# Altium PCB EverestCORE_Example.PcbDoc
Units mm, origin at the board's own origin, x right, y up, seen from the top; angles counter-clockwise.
Board outline 100 x 100 mm, 6 copper layers (Top Layer, Mid-Layer 1, Mid-Layer 2, Mid-Layer 3, Mid-Layer 4, Bottom Layer), stack 1.62 mm thick; 18 components, 52 nets, 312 pads, 67 vias.
Unrouted connection lines stored in the file: 17.
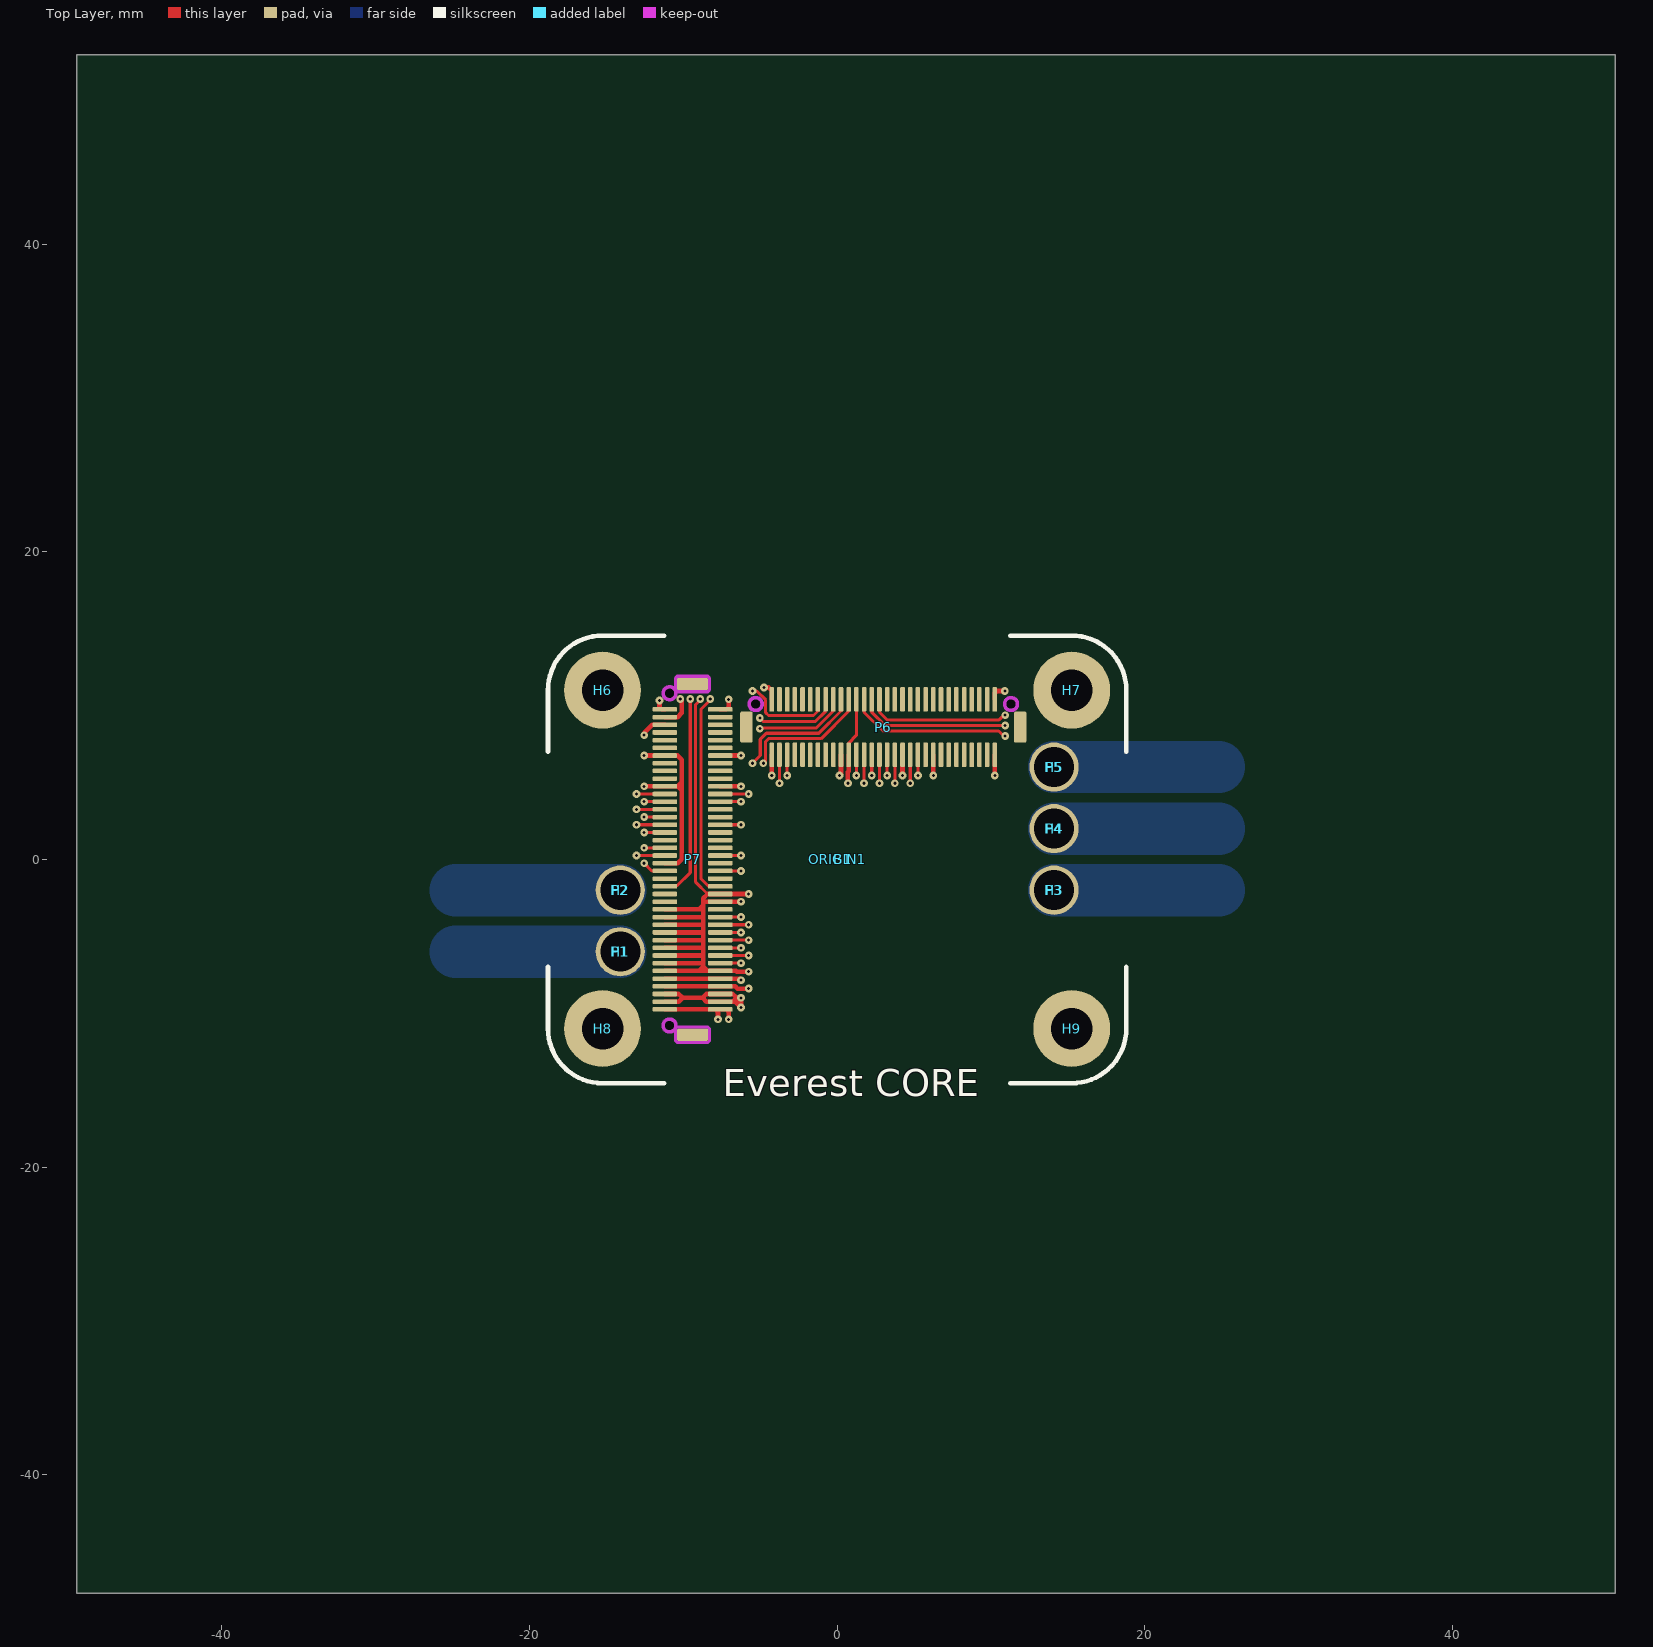
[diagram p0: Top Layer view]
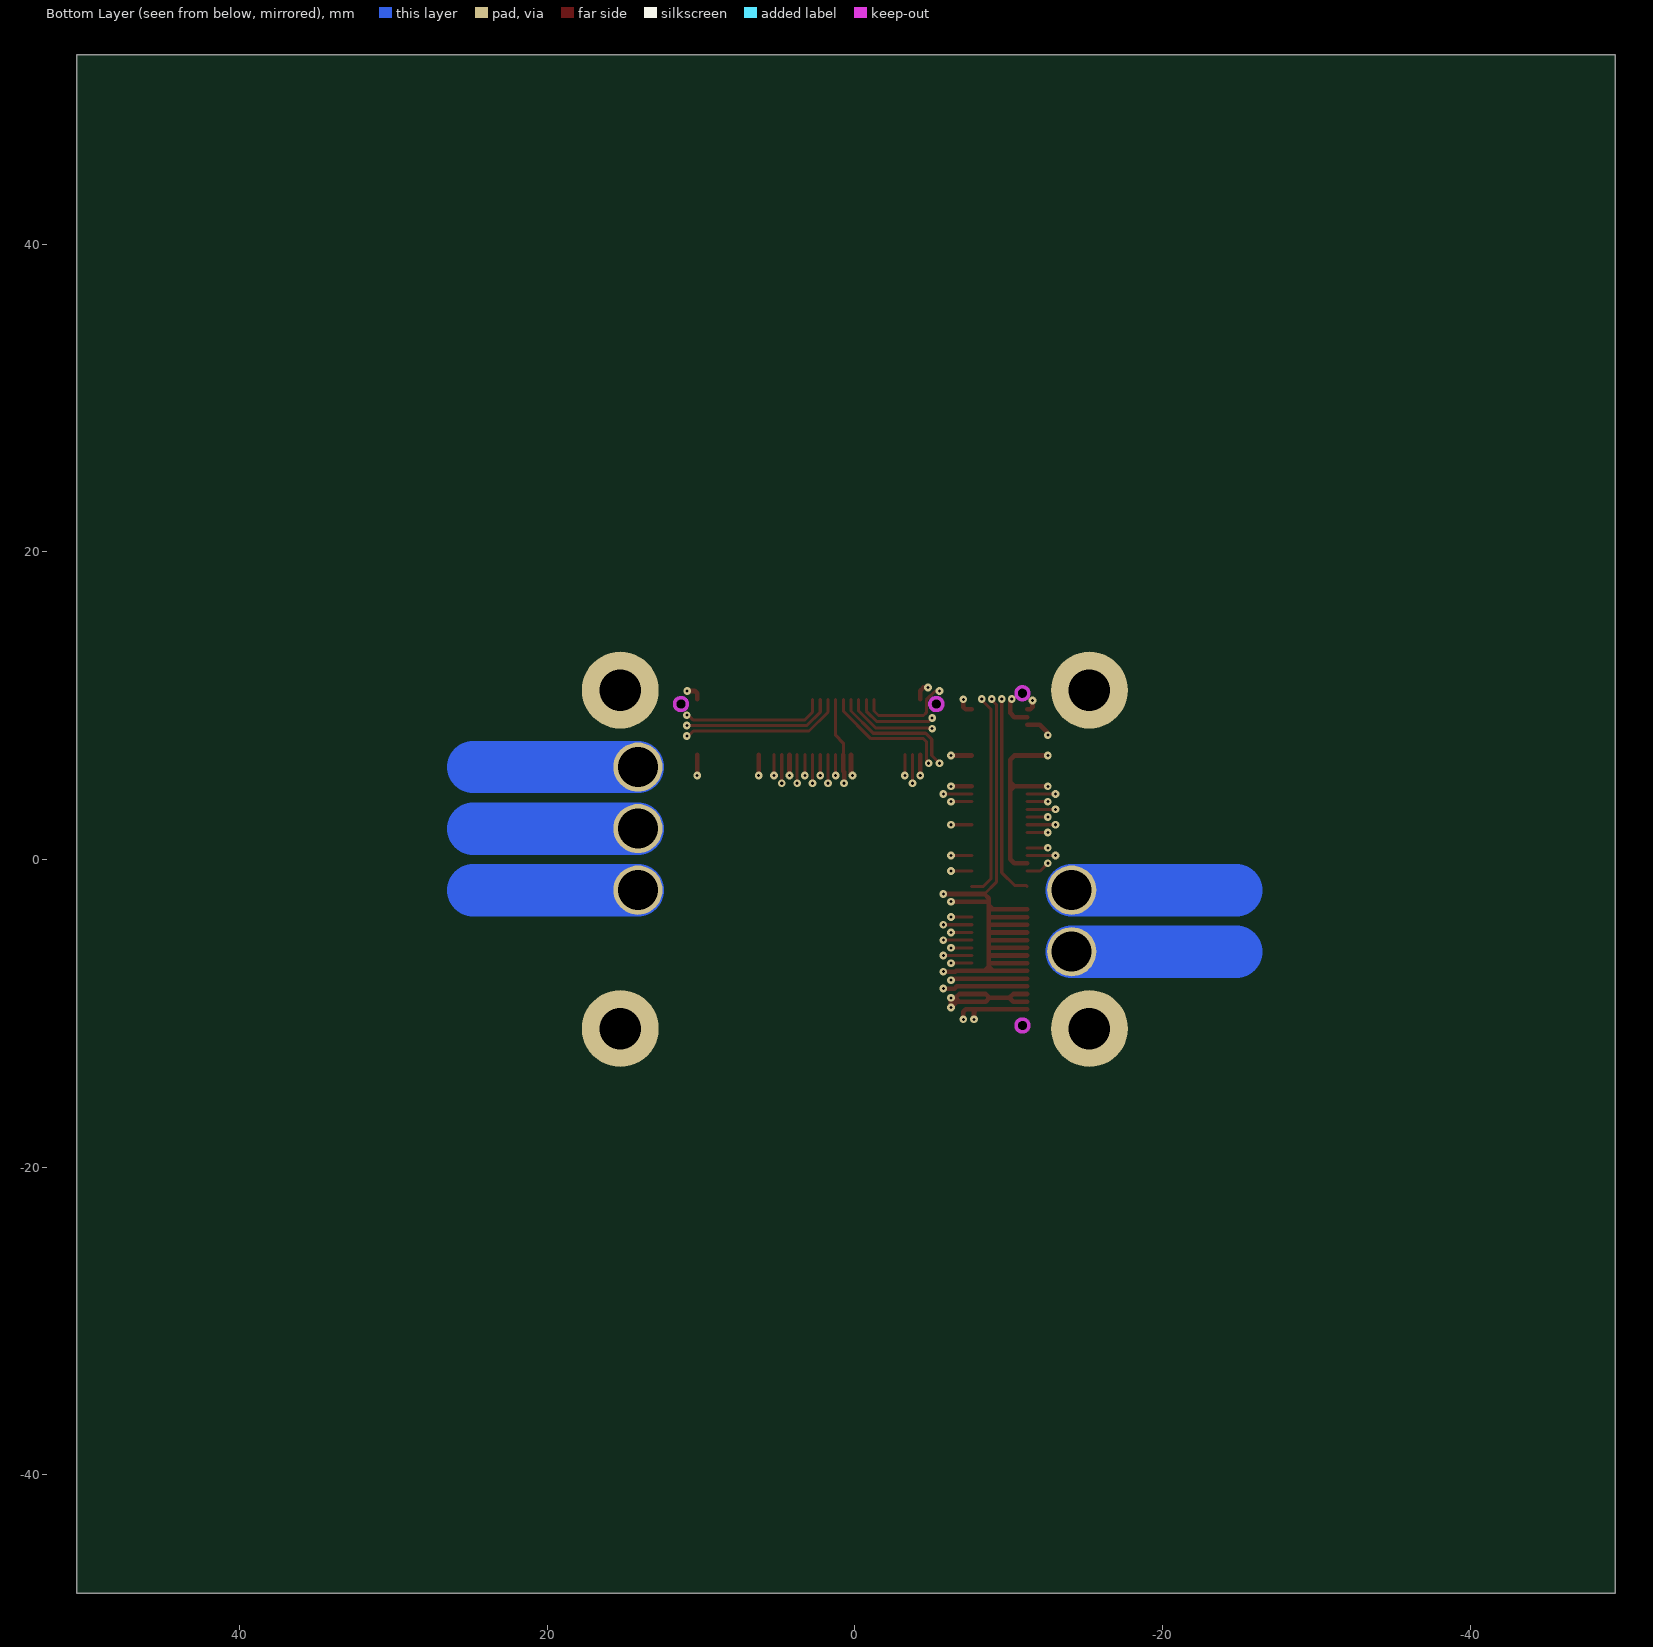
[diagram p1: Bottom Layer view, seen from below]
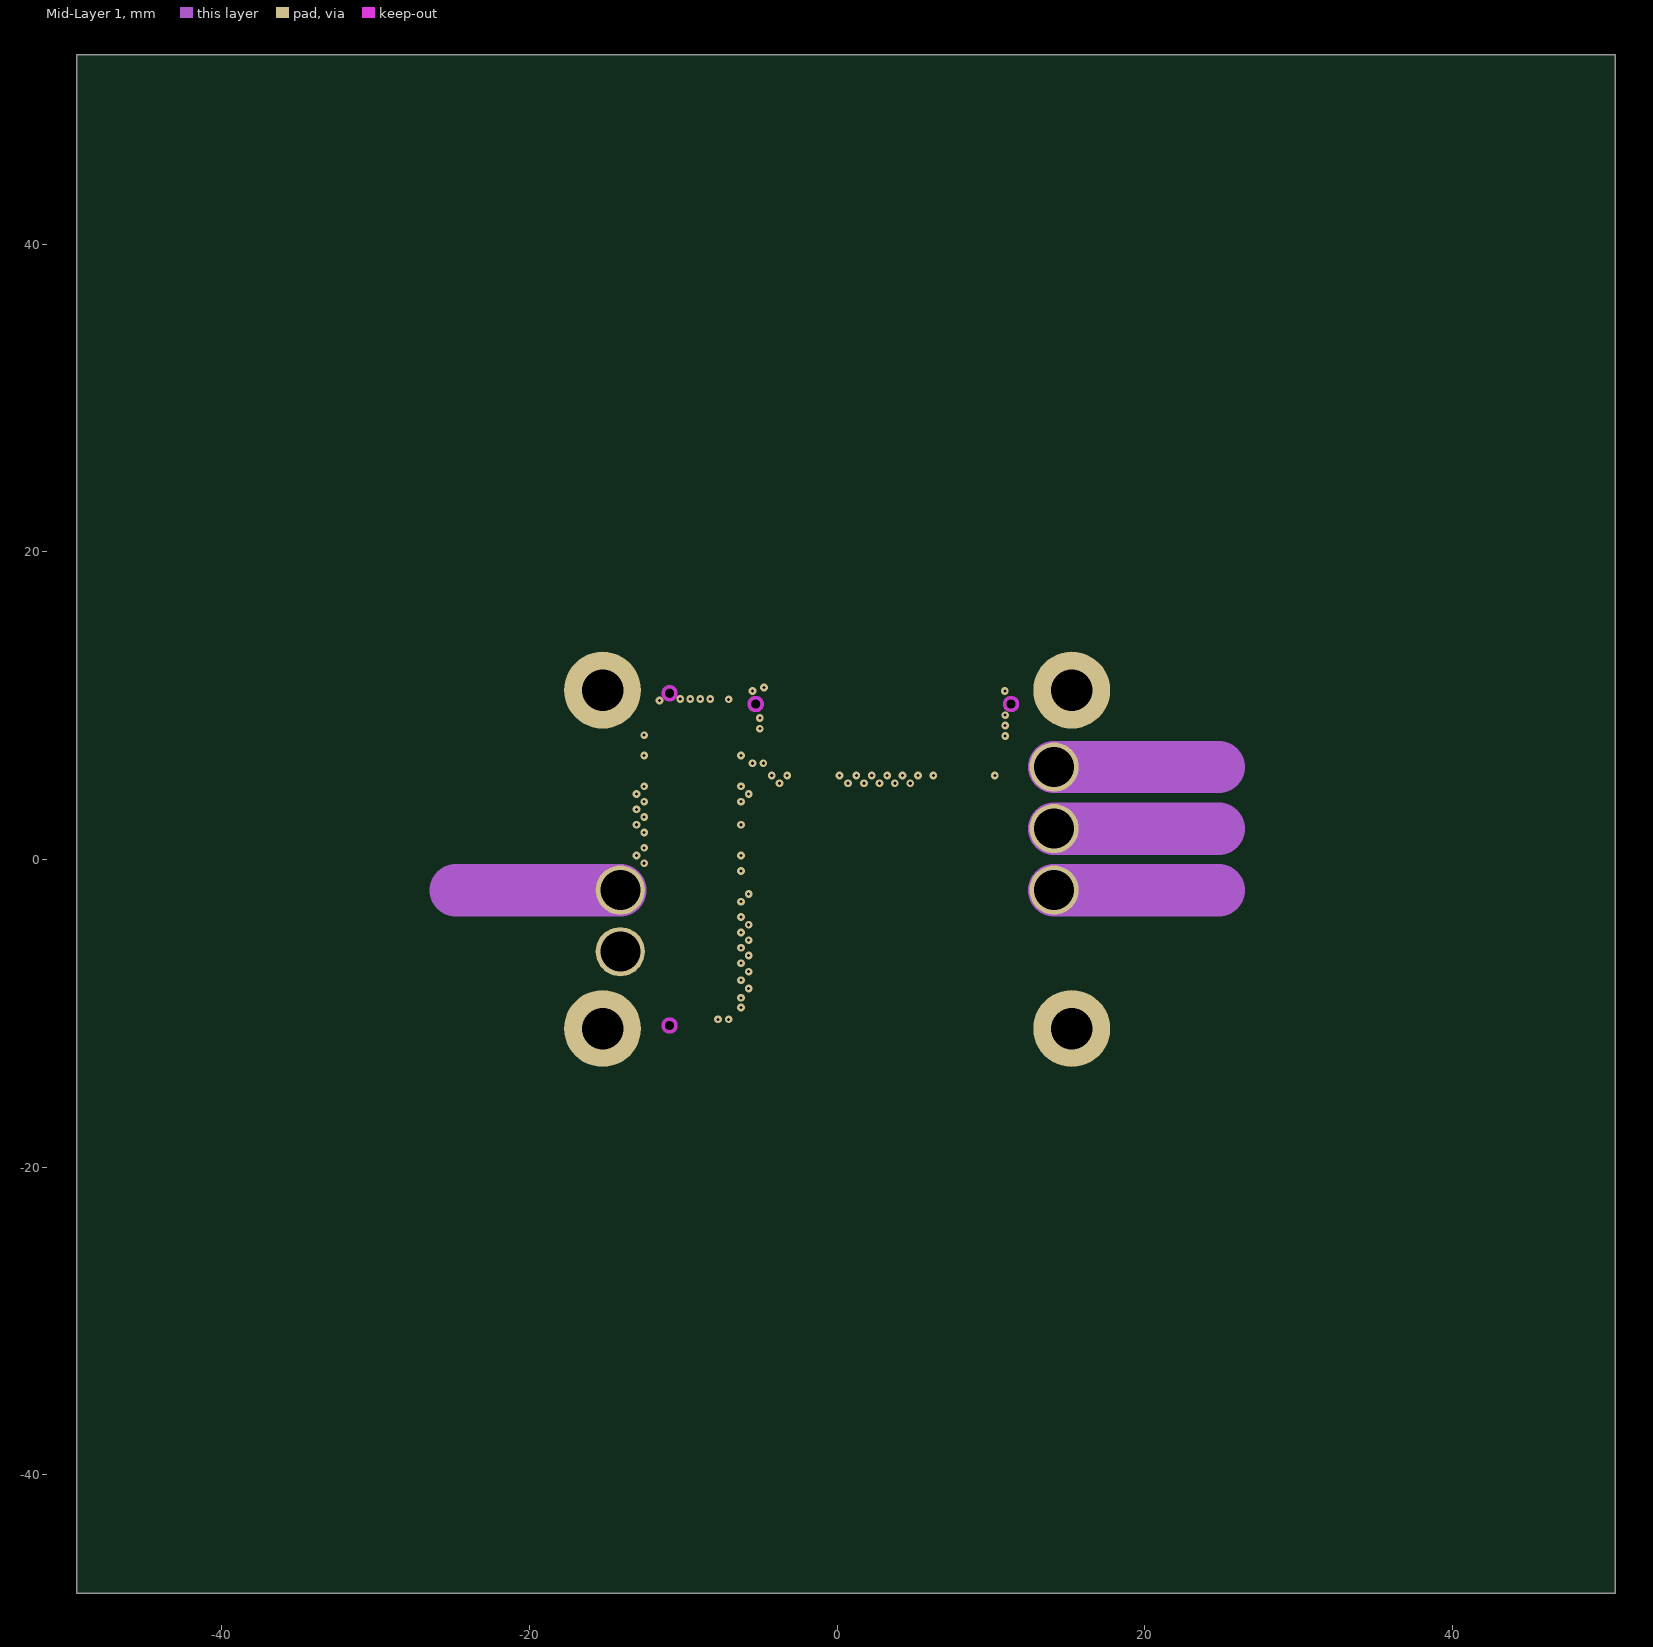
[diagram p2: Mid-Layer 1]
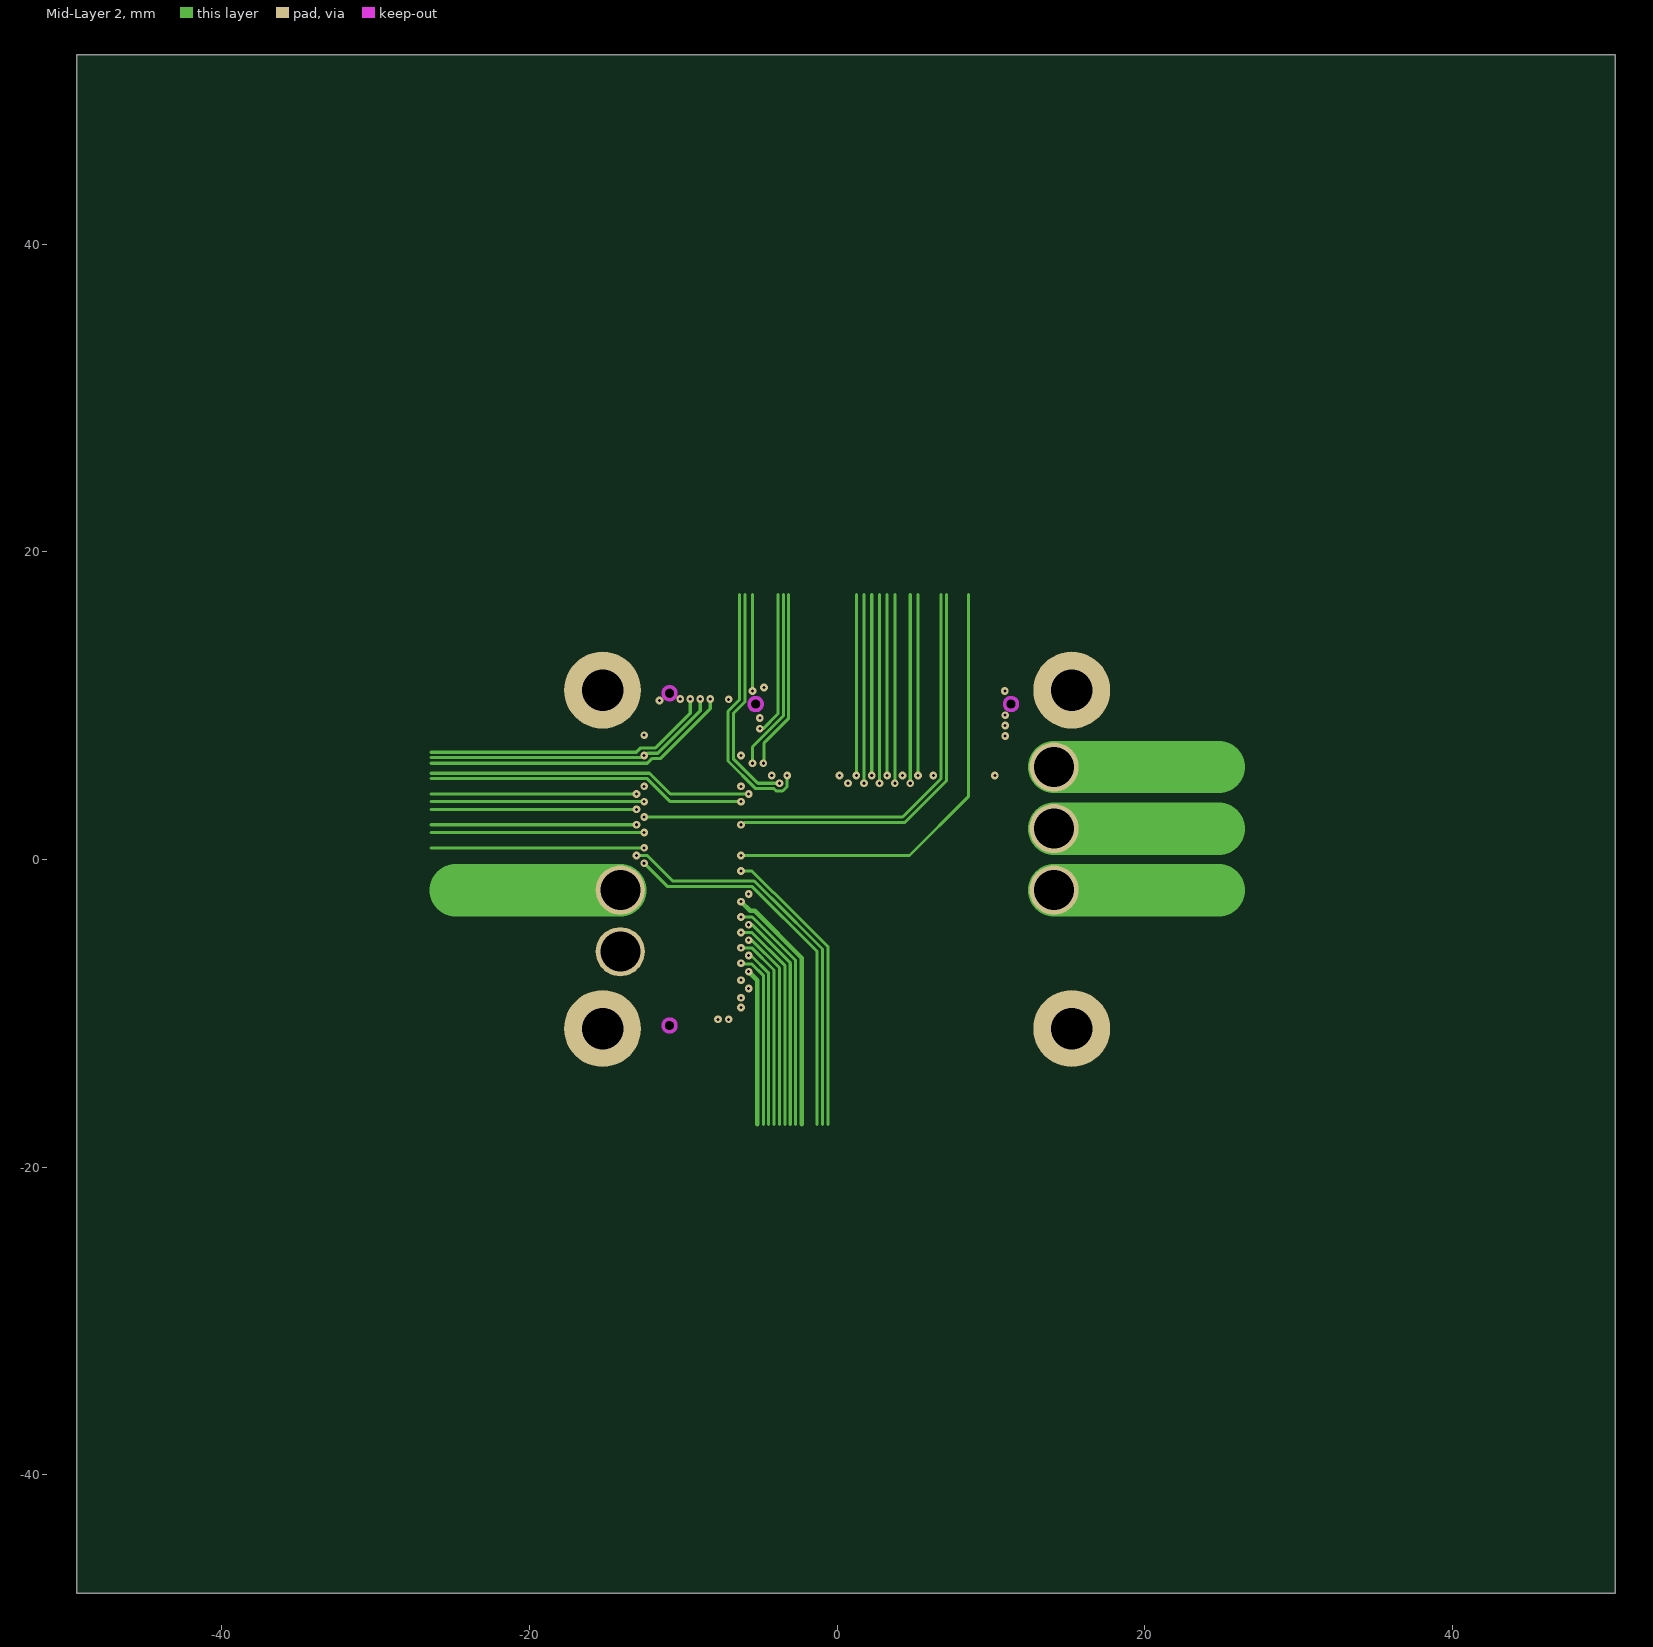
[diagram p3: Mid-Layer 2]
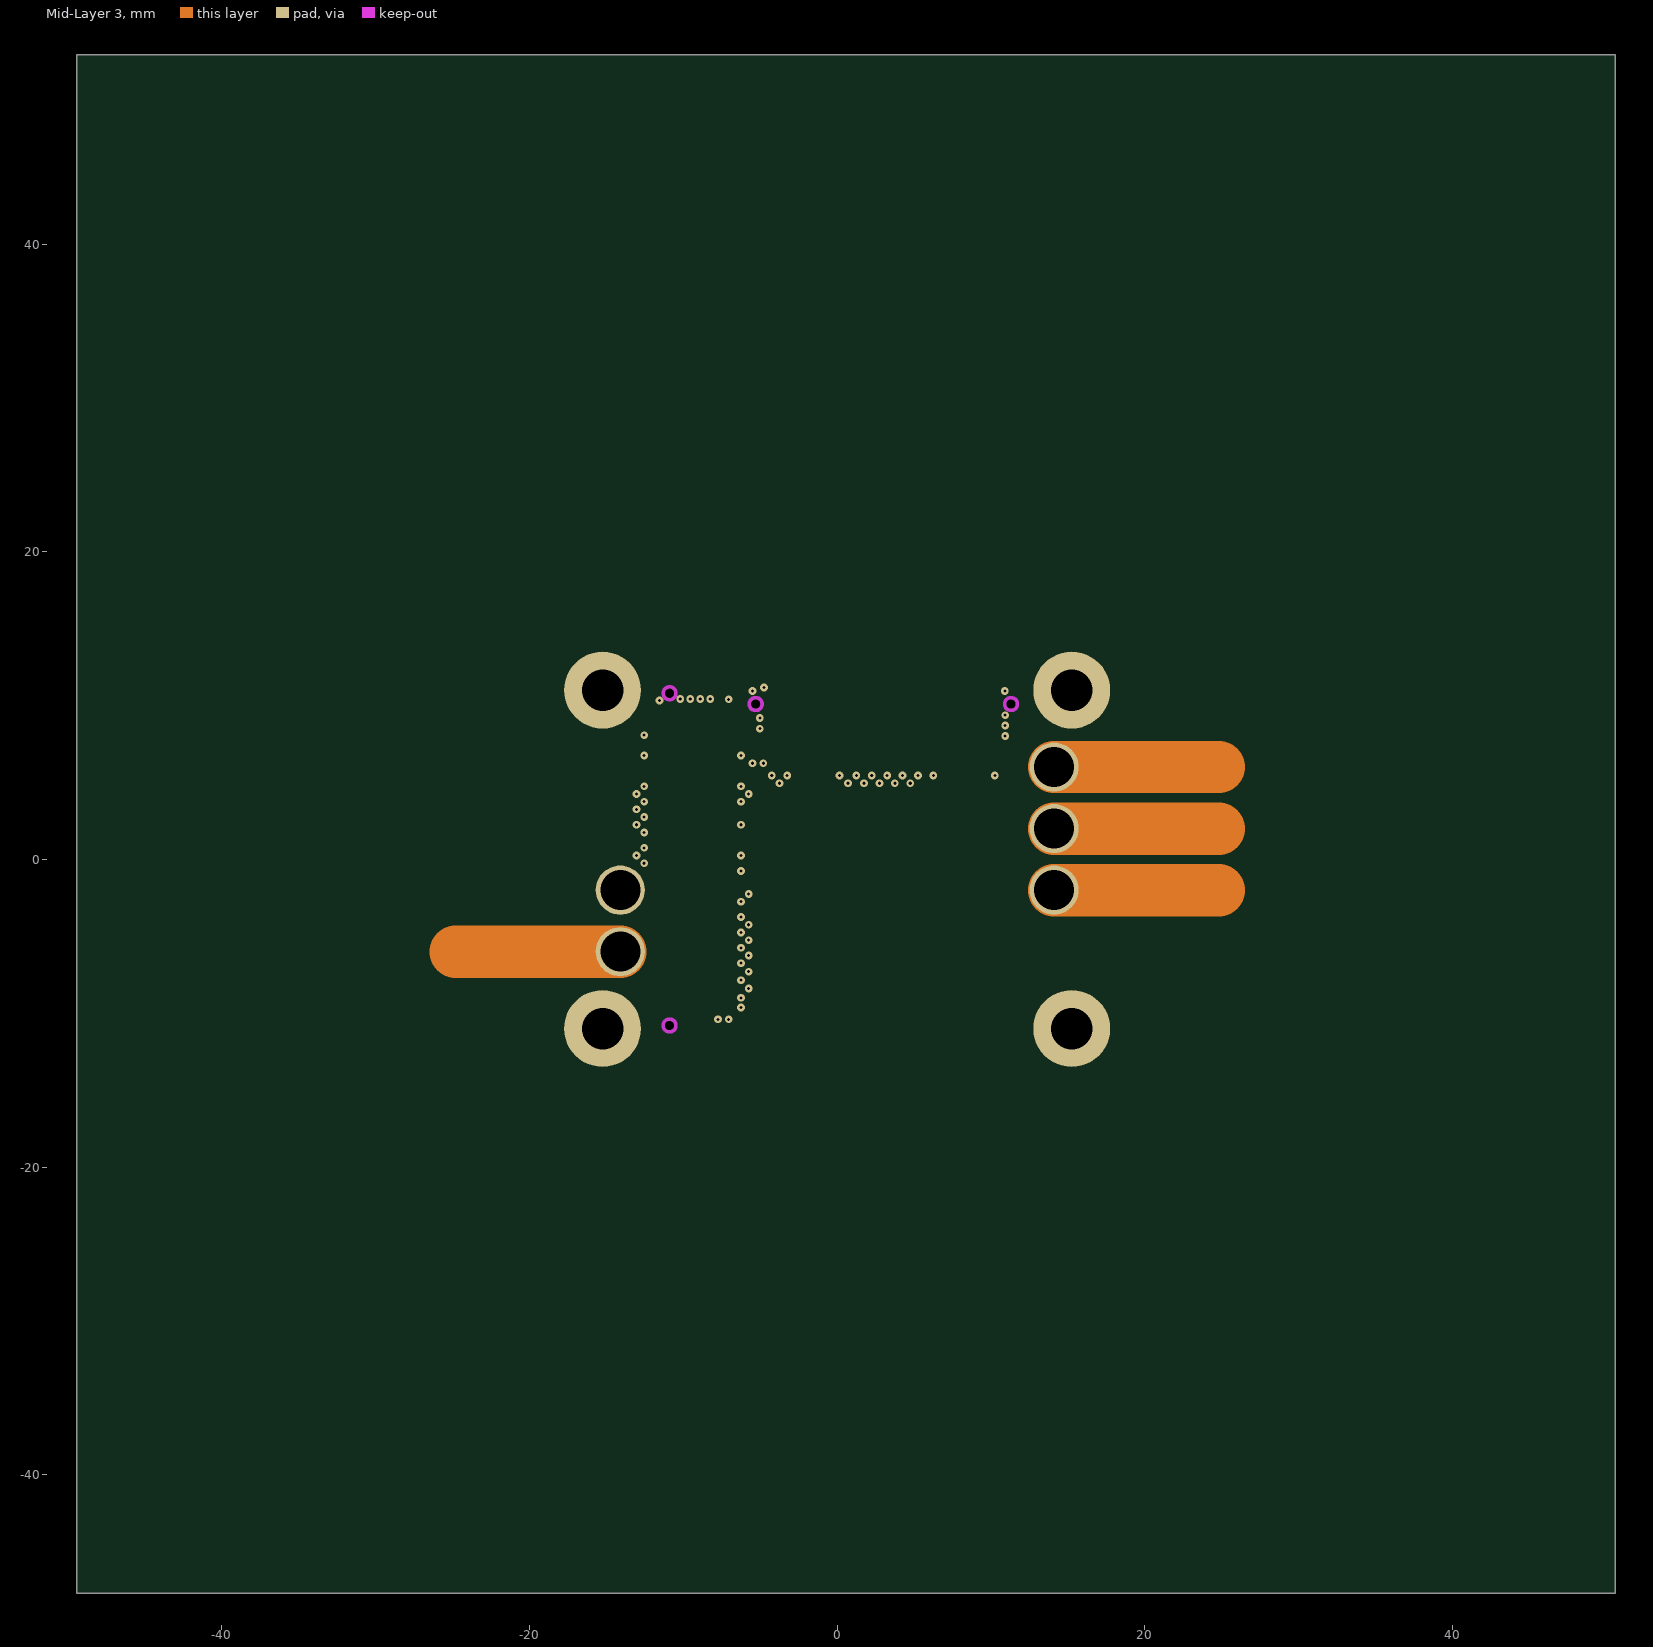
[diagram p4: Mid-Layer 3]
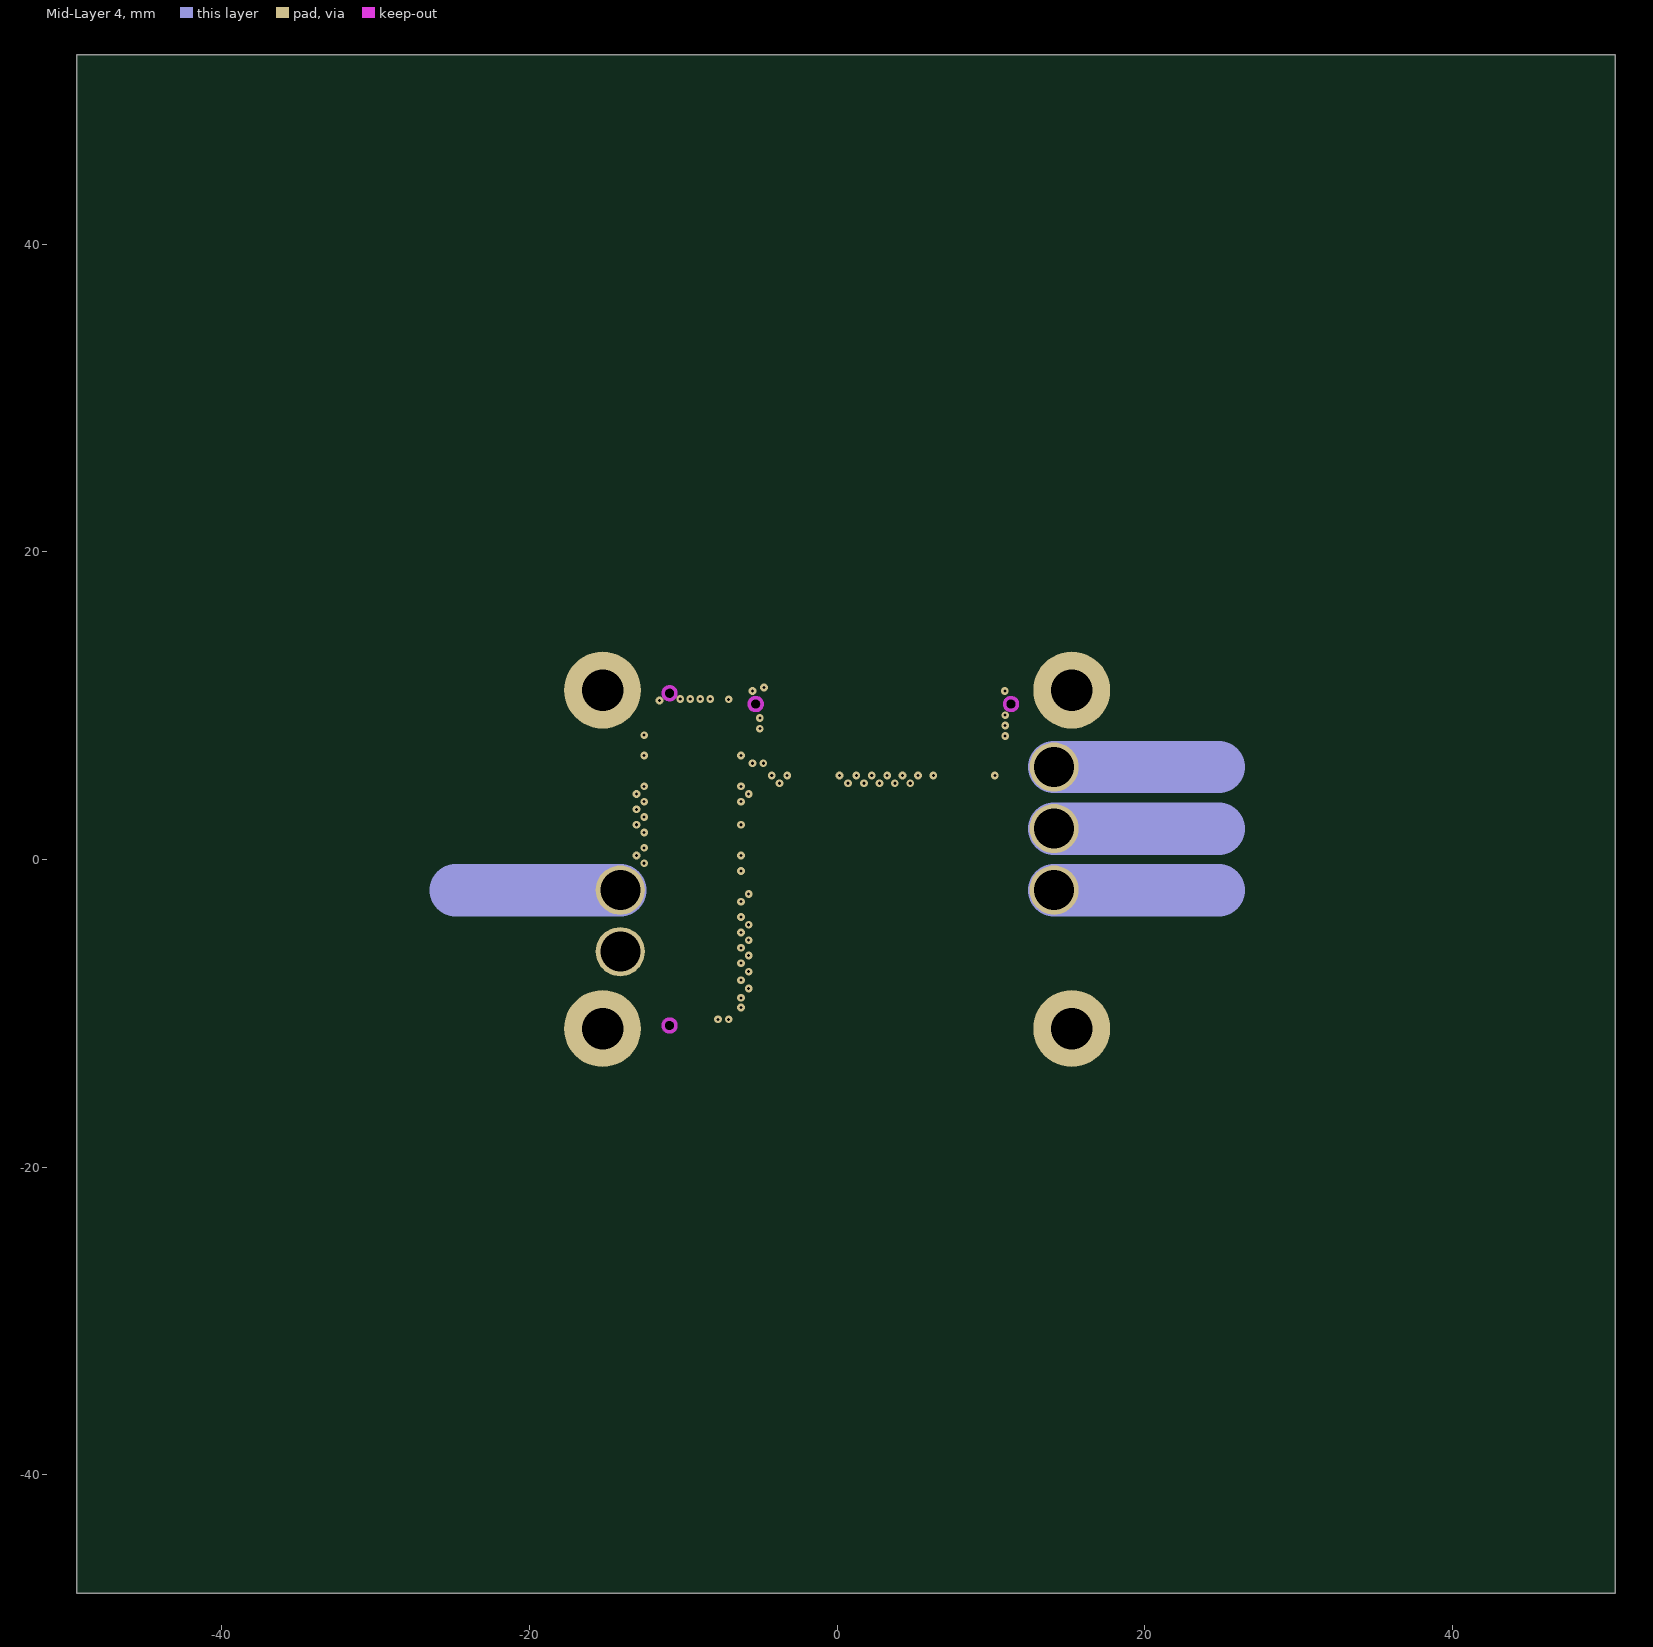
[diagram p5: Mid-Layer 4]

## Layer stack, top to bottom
Top Solder: solder mask 0.005, Solder Resist, Dk 3.5
Top Layer: signal copper 0.06
Dielectric 1: prepreg 0.22, FR-4 (tg > 150C), Dk 4.2
Mid-Layer 1: signal copper 0.035
Dielectric 2: core 0.35, FR-4 (tg > 150C), Dk 4.2
Mid-Layer 2: signal copper 0.035
Dielectric 3: prepreg 0.22, FR-4 (tg > 150C), Dk 4.2
Mid-Layer 3: signal copper 0.035
Dielectric 4: core 0.35, FR-4 (tg > 150C), Dk 4.2
Mid-Layer 4: signal copper 0.035
Dielectric 5: prepreg 0.22, FR-4 (tg > 150C), Dk 4.2
Bottom Layer: signal copper 0.06
Bottom Solder: solder mask 0.005, Solder Resist, Dk 3.5

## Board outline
-49.425,-47.7 50.575,-47.7 50.575,52.3 -49.425,52.3

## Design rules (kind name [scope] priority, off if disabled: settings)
AssemblyTestPointUsage [All] p1 off: valid=2
AssemblyTestpoint [All] p1 off: testpointundercomponent=TRUE minsize=1.016 maxsize=2.54 preferedsize=1.524 minholesize=0 maxholesize=1.016 preferedholesize=0.813 testpointgrid=0.025 usegrid=TRUE gridtolerance=0 allowsidetop=TRUE allowsidebottom=TRUE
Clearance "Keepout clearance" [All vs OnLayer('Keep-Out Layer') Or IsKeepOut Or Keepout] p1: gap=0.001 ignorepadtopadclearanceinfootprint=FALSE
Clearance HV [InNetClass('HighVoltage') vs OnOutside And NOT InNetClass('HighVoltageFloating')] p2: gap=0.5 ignorepadtopadclearanceinfootprint=TRUE
Clearance Clearance_PE [InNetClass('ProtectiveEarth')] p3: gap=0.5 ignorepadtopadclearanceinfootprint=TRUE
Clearance General [All] p4: gap=0.15 ignorepadtopadclearanceinfootprint=TRUE
ComponentClearance ComponentClearance_Excluded [All vs InComponent ('B1') OR InComponent('P1') OR InComponent('P2') OR InComponent('P3') OR InComponent('P4') OR InComponent('P5') OR InComponent('P6') OR InComponent('P7') OR InComponent('H1') OR InComponent('H2') OR InComponent('H3') OR InComponent('H4') OR InComponent('H5') OR InComponent('M1') OR InComponent('M2') OR InComponent('M3') OR InComponent('M4')] p1: gap=0 collisioncheckmode=3 verticalgap=0 showdistances=FALSE
ComponentClearance [All] p2: gap=0.2 collisioncheckmode=3 verticalgap=0.2 showdistances=FALSE
DiffPairsRouting [All] p1: maxlimit=1 minlimit=0.15 mostfreqgap=0.2 toplayer_minwidth=0.15 toplayer_maxwidth=0.3 toplayer_prefwidth=0.2 midlayer1_minwidth=0.15 midlayer1_maxwidth=0.3 midlayer1_prefwidth=0.2 midlayer2_minwidth=0.15 midlayer2_maxwidth=0.3 midlayer2_prefwidth=0.2 midlayer3_minwidth=0.15 midlayer3_maxwidth=0.3 midlayer3_prefwidth=0.2 midlayer4_minwidth=0.15 midlayer4_maxwidth=0.3 midlayer4_prefwidth=0.2 bottomlayer_minwidth=0.15 bottomlayer_maxwidth=0.3 bottomlayer_prefwidth=0.2 maxuncoupledlength=12.7
FabricationTestPointUsage [All] p1 off: valid=0 allowmultiple=FALSE
FabricationTestpoint [All] p1 off: side=3 testpointundercomponent=TRUE minsize=1.016 maxsize=2.54 preferedsize=1.524 minholesize=0 maxholesize=1.016 preferedholesize=0.813 testpointgrid=0.025 allowsidetop=TRUE allowsidebottom=TRUE usegrid=TRUE gridtolerance=0
FanoutControl Fanout_BGA [IsBGA] p1 off: bgadir=Out bgaviamode=Centered fanoutstyle=Auto fanoutdirection=Alternating viagrid=0.025 // Fanout_BGA (Default Rule)
FanoutControl Fanout_LCC [IsLCC] p2 off: bgadir=Out bgaviamode=Centered fanoutstyle=Auto fanoutdirection=Alternating viagrid=0.025 // Fanout_LCC (Default Rule)
FanoutControl Fanout_SOIC [IsSOIC] p3 off: bgadir=Out bgaviamode=Centered fanoutstyle=Auto fanoutdirection=Alternating viagrid=0.025 // Fanout_SOIC (Default Rule)
FanoutControl Fanout_Small [(CompPinCount < 5)] p4 off: bgadir=Out bgaviamode=Centered fanoutstyle=Auto fanoutdirection=OutThenIn viagrid=0.025 // Fanout_Small (Default Rule)
FanoutControl Fanout_Default [All] p5 off: bgadir=Out bgaviamode=Centered fanoutstyle=Auto fanoutdirection=Alternating viagrid=0.025 // Fanout_Default (Default Rule)
Height [All] p1: minheight=0 maxheight=30 prefheight=12.7
HoleSize [All] p1: absolutevalues=TRUE maxlimit=5 minlimit=0.1 maxpercent=80.000 minpercent=20.000
HoleToHoleClearance [All] p1: gap=0.3 allowstackedmicrovias=FALSE
MinimumAnnularRing [All] p1: minimumring=0.1
MinimumSolderMaskSliver [All] p1: minsoldermaskwidth=0.07
NetAntennae [All] p1: netantennaetolerance=2
PlaneClearance [All] p1: clearance=0.25
PlaneConnect [All] p1: planeconnectstyle=Relief reliefexpansion=0.5 reliefentries=4 reliefconductorwidth=0.25 reliefairgap=0.25
PolygonConnect [All] p1: connectstyle=Direct reliefconductorwidth=0.25 reliefentries=4 polygonreliefangle="90 Angle" airgapwidth=0.25
RoomDefinition EverestCORE_Module [InComponentClass('EverestCORE_Module')] p1: confinementstyle=ConfineIn formatcopy=TRUE lockcomponents=FALSE outline -128.805,-97.38 -78.005,-97.38 -78.005,-71.98 -128.805,-71.98
RoomDefinition Top [InComponentClass('Top')] p2 off: confinementstyle=ConfineIn formatcopy=TRUE lockcomponents=FALSE outline -128.805,-97.38 -78.005,-97.38 -78.005,-71.98 -128.805,-71.98
RoutingVias [All] p1: holewidth=0.2 width=0.6 viastyle="Through Hole" minholewidth=0.1 minwidth=0.3 maxholewidth=1 maxwidth=1.5
SilkToSilkClearance [All] p1 off: silktosilkclearance=0.1
SilkToSolderMaskClearance SilkscreenOverComponentPads [IsPad] p1 off: minsilkscreentomaskgap=0.05 clearancetoexposedcopper=TRUE
SolderMaskExpansion [All] p1: expansion=0.05
UnRoutedNet [All] p1: checkbadconnections=TRUE
Width [All] p1: maxlimit=80 minlimit=0.15 preferedwidth=0.2 checkconnectedcopper=TRUE
9 further rules are at their usual default settings.

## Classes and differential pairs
component class EverestCORE_Module: B1 H1 H2 H3 H4 H5 H6 H7 H8 H9 P1 P2 P3 P4 P5 P6 P7
net class ProtectiveEarth: PE1 PE2 PE3 PE4
net class HighVoltage: GND_P PH_A PH_B PH_C POW_SUP
net class HighCurrent: GND_P PH_A PH_B PH_C POW_SUP
component class Top: FD9 FD10 H10 H11 ORIGIN1 P? R42

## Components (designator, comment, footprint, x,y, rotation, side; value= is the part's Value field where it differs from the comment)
B1 "Everest_CORE" EVEREST_CORE 0,0 r0 top locked value=-
H1 "Part Number" Hole_1.7mm_Routing -14.1,-6 r0 top locked value=-
H2 "Part Number" Hole_1.7mm_Routing -14.1,-2 r0 top locked value=-
H3 "Part Number" Hole_1.7mm_Routing 14.1,-2 r0 top locked value=-
H4 "Part Number" Hole_1.7mm_Routing 14.1,2 r0 top locked value=-
H5 "Part Number" Hole_1.7mm_Routing 14.1,6 r0 top locked value=-
H6 "Part Number" Hole_2.7mm_Routing -15.25,11 r0 top locked value=-
H7 "Part Number" Hole_2.7mm_Routing 15.25,11 r0 top locked value=-
H8 "Part Number" Hole_2.7mm_Routing -15.25,-11 r0 top locked value=-
H9 "Part Number" Hole_2.7mm_Routing 15.25,-11 r0 top locked value=-
ORIGIN1 "ORIGIN" ORIGIN 0,0 r0 top locked value=-
P1 "Part Number" MillMax_9372-0-15-15-23-27-10-0_HD -14.1,-6 r0 top locked value=-
P2 "Part Number" MillMax_9372-0-15-15-23-27-10-0_HD -14.1,-2 r0 top locked value=-
P3 "Part Number" MillMax_9372-0-15-15-23-27-10-0_HD 14.1,-2 r0 top locked value=-
P4 "Part Number" MillMax_9372-0-15-15-23-27-10-0_HD 14.1,2 r0 top locked value=-
P5 "Part Number" MillMax_9372-0-15-15-23-27-10-0_HD 14.1,6 r0 top locked value=-
P6 "HIROSE_DF12(3.0)-60DS-0.5V(86)" HIROSE_DF12(3.0)-60DS-0.5V(86) 3,8.6 r0 top locked value=-
P7 "HIROSE_DF12(3.0)-80DS-0.5V(86)" HIROSE_DF12(3.0)-80DS-0.5V(86) -9.4,0 r90 top locked value=-

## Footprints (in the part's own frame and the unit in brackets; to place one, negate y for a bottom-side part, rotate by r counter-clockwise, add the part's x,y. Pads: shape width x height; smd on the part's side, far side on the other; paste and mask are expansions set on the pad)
EVEREST_CORE [mm] "Everest CORE 3D model + Pads + Connectors position"
  rrect20% 2x0.8 on Mech5: 0(-9.4,-11.4) 0(-9.4,11.4)
  rrect20% 0.8x2 on Mech5: 0(-5.9,8.6) 0(11.9,8.6)
  rrect50% 1.6x0.3 on Mech5: 1(-11.2,-9.75) 2(-7.6,-9.75) 3(-11.2,-9.25) 4(-7.6,-9.25) 5(-11.2,-8.75) 6(-7.6,-8.75) 7(-11.2,-8.25) 8(-7.6,-8.25) 9(-11.2,-7.75) 10(-7.6,-7.75) 11(-11.2,-7.25) 12(-7.6,-7.25) 13(-11.2,-6.75) 14(-7.6,-6.75) 15(-11.2,-6.25) 16(-7.6,-6.25) 17(-11.2,-5.75) 18(-7.6,-5.75) 19(-11.2,-5.25) 20(-7.6,-5.25) 21(-11.2,-4.75) 22(-7.6,-4.75) 23(-11.2,-4.25) 24(-7.6,-4.25) 25(-11.2,-3.75) 26(-7.6,-3.75) 27(-11.2,-3.25) 28(-7.6,-3.25) 29(-11.2,-2.75) 30(-7.6,-2.75) 31(-11.2,-2.25) 32(-7.6,-2.25) 33(-11.2,-1.75) 34(-7.6,-1.75) 35(-11.2,-1.25) 36(-7.6,-1.25) 37(-11.2,-0.75) 38(-7.6,-0.75) 39(-11.2,-0.25) 40(-7.6,-0.25) 41(-11.2,0.25) 42(-7.6,0.25) 43(-11.2,0.75) 44(-7.6,0.75) 45(-11.2,1.25) 46(-7.6,1.25) 47(-11.2,1.75) 48(-7.6,1.75) 49(-11.2,2.25) 50(-7.6,2.25) 51(-11.2,2.75) 52(-7.6,2.75) 53(-11.2,3.25) 54(-7.6,3.25) 55(-11.2,3.75) 56(-7.6,3.75) 57(-11.2,4.25) 58(-7.6,4.25) 59(-11.2,4.75) 60(-7.6,4.75) 61(-11.2,5.25) 62(-7.6,5.25) 63(-11.2,5.75) 64(-7.6,5.75) 65(-11.2,6.25) 66(-7.6,6.25) 67(-11.2,6.75) 68(-7.6,6.75) 69(-11.2,7.25) 70(-7.6,7.25) 71(-11.2,7.75) 72(-7.6,7.75) 73(-11.2,8.25) 74(-7.6,8.25) 75(-11.2,8.75) 76(-7.6,8.75) 77(-11.2,9.25) 78(-7.6,9.25) 79(-11.2,9.75) 80(-7.6,9.75)
  rrect50% 0.3x1.6 on Mech5: 1(-4.25,10.4) 2(-4.25,6.8) 3(-3.75,10.4) 4(-3.75,6.8) 5(-3.25,10.4) 6(-3.25,6.8) 7(-2.75,10.4) 8(-2.75,6.8) 9(-2.25,10.4) 10(-2.25,6.8) 11(-1.75,10.4) 12(-1.75,6.8) 13(-1.25,10.4) 14(-1.25,6.8) 15(-0.75,10.4) 16(-0.75,6.8) 17(-0.25,10.4) 18(-0.25,6.8) 19(0.25,10.4) 20(0.25,6.8) 21(0.75,10.4) 22(0.75,6.8) 23(1.25,10.4) 24(1.25,6.8) 25(1.75,10.4) 26(1.75,6.8) 27(2.25,10.4) 28(2.25,6.8) 29(2.75,10.4) 30(2.75,6.8) 31(3.25,10.4) 32(3.25,6.8) 33(3.75,10.4) 34(3.75,6.8) 35(4.25,10.4) 36(4.25,6.8) 37(4.75,10.4) 38(4.75,6.8) 39(5.25,10.4) 40(5.25,6.8) 41(5.75,10.4) 42(5.75,6.8) 43(6.25,10.4) 44(6.25,6.8) 45(6.75,10.4) 46(6.75,6.8) 47(7.25,10.4) 48(7.25,6.8) 49(7.75,10.4) 50(7.75,6.8) 51(8.25,10.4) 52(8.25,6.8) 53(8.75,10.4) 54(8.75,6.8) 55(9.25,10.4) 56(9.25,6.8) 57(9.75,10.4) 58(9.75,6.8) 59(10.25,10.4) 60(10.25,6.8)
  silkscreen extent -18.8,-14.55 18.8,14.55, body extent -17.25,-13 17.25,13, height 10.4
HIROSE_DF12(3.0)-60DS-0.5V(86) [mm] "CONN HEADER 60POS 5MM SMD 0.5MM"
  rrect50% 0.3x1.6 smd: 1(-7.25,1.8) 2(-7.25,-1.8) 3(-6.75,1.8) 4(-6.75,-1.8) 5(-6.25,1.8) 6(-6.25,-1.8) 7(-5.75,1.8) 8(-5.75,-1.8) 9(-5.25,1.8) 10(-5.25,-1.8) 11(-4.75,1.8) 12(-4.75,-1.8) 13(-4.25,1.8) 14(-4.25,-1.8) 15(-3.75,1.8) 16(-3.75,-1.8) 17(-3.25,1.8) 18(-3.25,-1.8) 19(-2.75,1.8) 20(-2.75,-1.8) 21(-2.25,1.8) 22(-2.25,-1.8) 23(-1.75,1.8) 24(-1.75,-1.8) 25(-1.25,1.8) 26(-1.25,-1.8) 27(-0.75,1.8) 28(-0.75,-1.8) 29(-0.25,1.8) 30(-0.25,-1.8) 31(0.25,1.8) 32(0.25,-1.8) 33(0.75,1.8) 34(0.75,-1.8) 35(1.25,1.8) 36(1.25,-1.8) 37(1.75,1.8) 38(1.75,-1.8) 39(2.25,1.8) 40(2.25,-1.8) 41(2.75,1.8) 42(2.75,-1.8) 43(3.25,1.8) 44(3.25,-1.8) 45(3.75,1.8) 46(3.75,-1.8) 47(4.25,1.8) 48(4.25,-1.8) 49(4.75,1.8) 50(4.75,-1.8) 51(5.25,1.8) 52(5.25,-1.8) 53(5.75,1.8) 54(5.75,-1.8) 55(6.25,1.8) 56(6.25,-1.8) 57(6.75,1.8) 58(6.75,-1.8) 59(7.25,1.8) 60(7.25,-1.8)
  round 0 hole 0.6 unplated: H1(-8.3,1.5) H2(8.3,1.5)
  rrect20% 0.8x2 smd: S1(-8.9,0) S2(8.9,0)
  Keep-Out Layer circle w0.23: c-8.3,1.5 r0.42
  Keep-Out Layer circle w0.23: c8.3,1.5 r0.42
  body extent -9.05,-2.3 9.05,2.3, height 2.2
HIROSE_DF12(3.0)-80DS-0.5V(86) [mm] "CONN HEADER 80POS 3MM SMD 0.5MM"
  rrect50% 0.3x1.6 smd paste+0 mask+0.05: 1(-9.75,1.8) 2(-9.75,-1.8) 3(-9.25,1.8) 4(-9.25,-1.8) 5(-8.75,1.8) 6(-8.75,-1.8) 7(-8.25,1.8) 8(-8.25,-1.8) 9(-7.75,1.8) 10(-7.75,-1.8) 11(-7.25,1.8) 12(-7.25,-1.8) 13(-6.75,1.8) 14(-6.75,-1.8) 15(-6.25,1.8) 16(-6.25,-1.8) 17(-5.75,1.8) 18(-5.75,-1.8) 19(-5.25,1.8) 20(-5.25,-1.8) 21(-4.75,1.8) 22(-4.75,-1.8) 23(-4.25,1.8) 24(-4.25,-1.8) 25(-3.75,1.8) 26(-3.75,-1.8) 27(-3.25,1.8) 28(-3.25,-1.8) 29(-2.75,1.8) 30(-2.75,-1.8) 31(-2.25,1.8) 32(-2.25,-1.8) 33(-1.75,1.8) 34(-1.75,-1.8) 35(-1.25,1.8) 36(-1.25,-1.8) 37(-0.75,1.8) 38(-0.75,-1.8) 39(-0.25,1.8) 40(-0.25,-1.8) 41(0.25,1.8) 42(0.25,-1.8) 43(0.75,1.8) 44(0.75,-1.8) 45(1.25,1.8) 46(1.25,-1.8) 47(1.75,1.8) 48(1.75,-1.8) 49(2.25,1.8) 50(2.25,-1.8) 51(2.75,1.8) 52(2.75,-1.8) 53(3.25,1.8) 54(3.25,-1.8) 55(3.75,1.8) 56(3.75,-1.8) 57(4.25,1.8) 58(4.25,-1.8) 59(4.75,1.8) 60(4.75,-1.8) 61(5.25,1.8) 62(5.25,-1.8) 63(5.75,1.8) 64(5.75,-1.8) 65(6.25,1.8) 66(6.25,-1.8) 67(6.75,1.8) 68(6.75,-1.8) 69(7.25,1.8) 70(7.25,-1.8) 71(7.75,1.8) 72(7.75,-1.8) 73(8.25,1.8) 74(8.25,-1.8) 75(8.75,1.8) 76(8.75,-1.8) 77(9.25,1.8) 78(9.25,-1.8) 79(9.75,1.8) 80(9.75,-1.8)
  round 0 hole 0.6 unplated: H1(-10.8,1.5) H2(10.8,1.5)
  rrect20% 0.8x2 smd: S1(-11.4,0) S2(11.4,0)
  Keep-Out Layer circle w0.23: c10.8,1.5 r0.42
  Keep-Out Layer circle w0.23: c-10.8,1.5 r0.42
  body extent -11.55,-2.3 11.55,2.3, height 2.2
Hole_1.7mm_Routing [mm] "Routing hole, plated, 1.7 mm hole diameter"
  round 2.7 hole 1.7 paste+0 mask+0.05: 1(0,0)
  Top Layer pour cut-out: 0,-1.85 -0.708,-1.709 -1.308,-1.308 -1.709,-0.708 -1.85,0 -1.85,0 -1.709,0.708 -1.308,1.308 -0.708,1.709 0,1.85 0,1.85 0.708,1.709 1.308,1.308 1.709,0.708 1.85,0 1.85,0 1.709,-0.708 1.308,-1.308 0.708,-1.709 0,-1.85
  Top Layer pour cut-out: 0,-0.8 -0.306,-0.739 -0.566,-0.566 -0.739,-0.306 -0.8,0 -0.8,0 -0.739,0.306 -0.566,0.566 -0.306,0.739 0,0.8 0,0.8 0.306,0.739 0.566,0.566 0.739,0.306 0.8,0 0.8,0 0.739,-0.306 0.566,-0.566 0.306,-0.739 0,-0.8
  Bottom Layer pour cut-out: 0,-1.85 -0.708,-1.709 -1.308,-1.308 -1.709,-0.708 -1.85,0 -1.85,0 -1.709,0.708 -1.308,1.308 -0.708,1.709 0,1.85 0,1.85 0.708,1.709 1.308,1.308 1.709,0.708 1.85,0 1.85,0 1.709,-0.708 1.308,-1.308 0.708,-1.709 0,-1.85
  Bottom Layer pour cut-out: 0,-0.8 -0.306,-0.739 -0.566,-0.566 -0.739,-0.306 -0.8,0 -0.8,0 -0.739,0.306 -0.566,0.566 -0.306,0.739 0,0.8 0,0.8 0.306,0.739 0.566,0.566 0.739,0.306 0.8,0 0.8,0 0.739,-0.306 0.566,-0.566 0.306,-0.739 0,-0.8
  body extent -0.01,-0.01 0.01,0.01, height 0.01
Hole_2.7mm_Routing [mm] "Routing hole, plated, 2.7mm diameter"
  round 5 hole 2.7: 1(0,0)
  Top Layer pour cut-out: 0,3.511 1.339,3.244 2.475,2.486 3.234,1.35 3.5,0.011 3.5,0.011 3.5,-0.011 3.234,-1.35 2.475,-2.486 1.339,-3.244 0,-3.511 0,-3.511 -1.344,-3.244 -2.483,-2.483 -3.244,-1.344 -3.511,0 -3.511,0 -3.244,1.344 -2.483,2.483 -1.344,3.244 0,3.511
  Bottom Layer pour cut-out: 0,3.511 1.339,3.244 2.475,2.486 3.234,1.35 3.5,0.011 3.5,0.011 3.5,-0.011 3.234,-1.35 2.475,-2.486 1.339,-3.244 0,-3.511 0,-3.511 -1.344,-3.244 -2.483,-2.483 -3.244,-1.344 -3.511,0 -3.511,0 -3.244,1.344 -2.483,2.483 -1.344,3.244 0,3.511
  Multi-Layer pour cut-out: 0,3.5 1.339,3.234 2.475,2.475 3.234,1.339 3.5,0 3.5,0 3.234,-1.339 2.475,-2.475 1.339,-3.234 0,-3.5 0,-3.5 -1.339,-3.234 -2.475,-2.475 -3.234,-1.339 -3.5,0 -3.5,0 -3.234,1.339 -2.475,2.475 -1.339,3.234 0,3.5
  body extent -0.01,-0.01 0.01,0.01, height 0.01
MillMax_9372-0-15-15-23-27-10-0_HD [mm] "MillMax receptacle for MillMax 6142, gold plated, pass-through"
  round 3.2 hole 2.6: 1(0,0)
  body extent -1.5,-1.5 1.5,1.5, height 0.32
ORIGIN [mm] "Origin of coordinate axes for pick and place"
  round 0.5 on Mech16 paste+0 mask+0: 1(0,0) 1(0,0)
  round 0.5 on Mech10 paste+0 mask+0: 1(0,0) 1(0,0)
  round 0.5 on Mech11 paste+0 mask+0: 1(0,0) 1(0,0)
  body extent 0,0 0,0

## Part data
B1: library part EVEREST_CORE, "Everest CORE high-performance Servo Drive from Ingenia Motion Control.", ManufacturerName=Ingenia, ManufacturerPN=EVE-CORE, Package Type=-, TemperatureMaxC=85, TemperatureMinC=-40
H1 H2 H3 H4 H5: library part Hole_1.7mm_Routing, "Mounting, plated hole, 1.7 mm diameter", ManufacturerName=Ingenia, ManufacturerPN=-, Package Type=NO, TemperatureMaxC=0
H6 H7 H8 H9: library part Hole_2.7mm_Routing, "Mounting, plated hole, 2.7 mm diameter", ManufacturerName=Ingenia, ManufacturerPN=-, Package Type=NO
ORIGIN1: "Origin of coordinate axes for pick and place", ManufacturerName=-, TemperatureMaxC=200, TemperatureMinC=-60
P1 P2 P3 P4 P5: library part "Header 1", "1pin, receptacle for MillMax 6142, pass-through", ManufacturerName=MillMax, ManufacturerPN=9372-0-15-15-23-27-10-0, Package Name=MillMax_9372-0-15-15-23-27-10-0, Package Type=TH, Supplier Part Number 1=ED1048-ND, TemperatureMaxC=125, TemperatureMinC=-55
P6: library part Header_30X2_MALE, "Connector SMD Mezzanine, 60 ways, 0.5mm pitch, 3mm stack height. Male", ManufacturerName=Hirose, ManufacturerPN=DF12(3.0)-60DS-0.5V(86), Package Name="SMD connector 60 ways", Package Type=SM, Supplier Part Number 1=H5207CT-ND, TemperatureMaxC=125, TemperatureMinC=-45
P7: library part Header_40x2_MALE, "Connector SMD Mezzanine, 80 ways, 0.5mm pitch, 3mm stack height. Male with metal fitting and boss", ManufacturerName=Hirose, ManufacturerPN=DF12(3.0)-80DS-0.5V(86), Package Name="SMD connector 80 ways male", Package Type=SM, Supplier Part Number 1=H5208CT-ND, TemperatureMaxC=125, TemperatureMinC=-45

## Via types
v1: diameter 0.5, hole 0.2, Top Layer to Bottom Layer, 67 vias

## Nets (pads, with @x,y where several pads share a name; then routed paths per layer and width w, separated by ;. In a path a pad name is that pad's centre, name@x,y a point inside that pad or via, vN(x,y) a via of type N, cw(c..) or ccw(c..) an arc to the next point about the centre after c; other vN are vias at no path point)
+1.65V_REF: P7.75 | length 1.7
  Top Layer w0.3: v1(-12.55,8.075) -12.55,8.23 -12.03,8.75 P7.75
+3.3V_D: P6.25 P6.29 P7.9 P7.10 | length 25
  Top Layer w0.2: P6.25 1.75,9.575 2.975,8.35 10.497,8.35 10.822,8.025 v1(10.925,8.025) ; P6.29 2.75,9.57 3.27,9.05 10.497,9.05 10.822,9.375 v1(10.925,9.375)
  Top Layer w0.3: P7.9 P7.10 -6.35,-7.75 v1(-6.25,-7.85)
+3.3V_REF: P7.77 | length 2.2
  Top Layer w0.3: P7.77 -10.37,9.25 -10.1,9.52 -10.1,10.325 v1(-10.2,10.425)
+5V_D: P7.3 P7.4 P7.5 P7.6 | length 11
  Top Layer w0.3: P7.3 -10.3,-9.25 -10.05,-9 ; P7.5 -10.3,-8.75 -10.05,-9 ; v1(-6.25,-9.625) -6.625,-9.25 -6.775,-9.25 ; -10.05,-9 -8.75,-9 ; -8.75,-9 -8.5,-8.75 P7.6 -6.775,-8.75 -6.525,-9 ; -8.75,-9 -8.5,-9.25 P7.4 -6.775,-9.25 ; -6.775,-9.25 -6.525,-9 ; -6.525,-9 -6.525,-9.349 -6.25,-9.624 v1(-6.25,-9) -6.525,-9
\EXT_FAULT: P7.41 | length 27.9
  Top Layer w0.2: v1(-13.05,0.25) P7.41
  Mid-Layer 2 w0.2: v1(-13.05,0.25) -12.343,0.25 -10.693,-1.4 -5.398,-1.4 -4.298,-2.5 -4.275,-2.5 -0.95,-5.825 -0.95,-17.225
\HW_RESET: P7.38 | length 20.6
  Top Layer w0.2: P7.38 v1(-6.25,-0.75)
  Mid-Layer 2 w0.2: v1(-6.25,-0.75) -5.553,-0.75 -4.153,-2.15 -4.13,-2.15 -0.6,-5.68 -0.6,-17.225
\MCB_SPI_CS: P7.18 | length 14.1
  Top Layer w0.2: P7.18 v1(-6.25,-5.75)
  Mid-Layer 2 w0.2: v1(-6.25,-5.75) -5.543,-5.75 -4.1,-7.193 -4.1,-17.225
\STO1: P7.33 | length 32.1
  Top Layer w0.2: P7.33 -11.15,-1.7 -10.39,-1.7 -9.55,-0.86 v1(-9.55,10.425)
  Mid-Layer 2 w0.2: -26.4,6.966 -13.059,6.966 -12.775,7.25 -11.8,7.25 -9.55,9.5 v1(-9.55,10.425)
\STO2: P7.34 | length 33.6
  Top Layer w0.2: v1(-8.25,10.425) -8.25,10.36 -8.85,9.76 -8.85,-1.26 -8.36,-1.75 P7.34
  Mid-Layer 2 w0.2: -26.4,6.25 -12.343,6.25 -12.043,6.55 -11.5,6.55 -8.25,9.8 v1(-8.25,10.425)
ABSENC1_CLK: P6.38 | length 14.1
  Top Layer w0.2: v1(4.75,4.95) P6.38
  Mid-Layer 2 w0.2: v1(4.75,4.95) 4.75,17.225
ABSENC1_DATA: P6.40 | length 13.1
  Top Layer w0.2: v1(5.25,5.45) P6.40
  Mid-Layer 2 w0.2: v1(5.25,5.45) 5.25,17.225
ABSENC2_CLK: P7.50 | length 28
  Top Layer w0.2: P7.50 v1(-6.25,2.25)
  Mid-Layer 2 w0.2: v1(-6.25,2.25) -6.169,2.25 -6.019,2.4 4.402,2.4 7.1,5.098 7.1,17.225
ABSENC2_DATA: P7.51 | length 33.7
  Top Layer w0.2: v1(-12.55,2.75) P7.51
  Mid-Layer 2 w0.2: v1(-12.55,2.75) 4.257,2.75 6.75,5.243 6.75,17.225
AN1_N: P6.6 | length 18
  Top Layer w0.2: v1(-3.25,5.45) P6.6
  Mid-Layer 2 w0.2: -6.35,17.225 -6.35,10.375 -7.1,9.625 -7.1,6.398 -5.302,4.6 -4.107,4.6 -3.957,4.45 -3.543,4.45 -3.25,4.743 v1(-3.25,5.45)
AN1_P: P6.4 | length 16.5
  Top Layer w0.2: v1(-3.75,4.95) P6.4
  Mid-Layer 2 w0.2: -6,17.225 -6,10.23 -6.75,9.48 -6.75,6.543 -5.157,4.95 v1(-3.75,4.95)
DIG_ENC_1A: P6.24 | length 13.1
  Top Layer w0.2: v1(1.25,5.45) P6.24
  Mid-Layer 2 w0.2: v1(1.25,5.45) 1.25,17.225
DIG_ENC_1B: P6.26 | length 14.1
  Top Layer w0.2: v1(1.75,4.95) P6.26
  Mid-Layer 2 w0.2: v1(1.75,4.95) 1.75,17.225
DIG_ENC_1Z: P6.28 | length 13.1
  Top Layer w0.2: v1(2.25,5.45) P6.28
  Mid-Layer 2 w0.2: v1(2.25,5.45) 2.25,17.225
DIG_ENC_2A: P6.30 | length 14.1
  Top Layer w0.2: v1(2.75,4.95) P6.30
  Mid-Layer 2 w0.2: v1(2.75,4.95) 2.75,17.225
DIG_ENC_2B: P6.32 | length 13.1
  Top Layer w0.2: v1(3.25,5.45) P6.32
  Mid-Layer 2 w0.2: v1(3.25,5.45) 3.25,17.225
DIG_ENC_2Z: P6.34 | length 14.1
  Top Layer w0.2: v1(3.75,4.95) P6.34
  Mid-Layer 2 w0.2: v1(3.75,4.95) 3.75,17.225
FAULT_SIGNAL: P7.37 | length 26.4
  Top Layer w0.2: v1(-12.55,-0.25) -12.05,-0.75 P7.37
  Mid-Layer 2 w0.2: v1(-12.55,-0.25) -11.05,-1.75 -5.543,-1.75 -1.3,-5.993 -1.3,-17.225
GND_A: P6.1 P6.2 P6.20 P7.79 P7.80 | length 5.8
  Top Layer w0.3: v1(-11.55,10.325) -11.55,9.9 -11.4,9.75 P7.79 ; P7.80 -7.2,9.75 -7.05,9.9 v1(-7.05,10.4) ; v1(-4.75,11.175) -4.461,11.175 -4.25,10.964 P6.1 ; v1(-4.25,5.45) P6.2 ; v1(0.15,5.45) 0.25,5.55 P6.20
GND_D: P6.15 P6.22 P6.23 P6.27 P6.36 P6.44 P6.59 P6.60 P7.1 P7.2 P7.7 P7.8 P7.11 P7.12 P7.13 P7.15 P7.17 P7.19 P7.21 P7.23 P7.25 P7.27 P7.30 P7.32 P7.39 P7.59 P7.60 P7.67 P7.68 | length 148.6
  Top Layer w0.2: v1(-8.9,10.425) -8.9,10.368 -9.2,10.068 -9.2,-1.48 -8.43,-2.25 ; v1(-5.025,9.189) -4.786,8.95 -1.435,8.95 -0.75,9.635 P6.15 ; P6.22 0.75,7.56 1.25,8.06 P6.23 ; P6.27 2.25,9.575 3.125,8.7 v1(10.925,8.7)
  Top Layer w0.3: v1(-12.55,4.75) P7.59 -10.37,4.75 ; v1(-12.55,6.75) P7.67 -10.37,6.75 -10.1,6.48 -10.1,5.02 ; P7.1 P7.2 -7.2,-9.75 -7.05,-9.9 v1(-7.05,-10.4) ; P7.7 P7.8 -6.628,-8.25 -6.478,-8.4 v1(-5.75,-8.4) ; P7.11 -8.43,-7.25 ; P7.13 -8.702,-6.75 ; P7.15 -8.702,-6.25 ; P7.17 -8.702,-5.75 ; P7.19 -8.702,-5.25 ; P7.21 -8.702,-4.75 ; P7.23 -8.702,-4.25 ; P7.25 -8.702,-3.75 ; P7.27 -8.975,-3.25 ; P7.39 -10.37,-0.25 -10.1,0.02 -10.1,4.48 ; -8.97,-7.25 -8.7,-6.98 ; -8.705,-2.98 -8.975,-3.25 ; -8.702,-3.25 -8.975,-3.25 ; -8.7,-2.75 v1(-6.25,-2.75) ; P7.2@-7.9,-9.75 -7.75,-9.9 v1(-7.75,-10.4) ; P7.60 v1(-6.25,4.75) ; P7.68 v1(-6.25,6.75) ; v1(-5.75,-7.3) -6.525,-7.3 -6.575,-7.25 P7.12 -8.43,-7.25 ; v1(-5.75,-2.25) P7.32 -8.43,-2.25 -8.7,-2.52 -8.7,-6.98 ; v1(0.7,4.95) 0.7,5.678 0.75,5.728 P6.22 ; v1(4.25,5.45) P6.36 ; v1(6.25,5.45) P6.44 ; v1(10.25,5.45) P6.60 ; P6.59 10.25,10.8 10.4,10.95 v1(10.9,10.95) ; -10.37,4.75 -10.1,5.02 ; -10.37,4.75 -10.1,4.48 ; -10.1,4.48 -10.1,5.02 ; -8.7,-6.98 -8.43,-7.25
  Mid-Layer 2 w0.2: -26.4,6.616 -12.684,6.616 v1(-12.55,6.75) -12.469,6.75 -12.319,6.9 -11.655,6.9 -8.9,9.655 v1(-8.9,10.425)
  Mid-Layer 2 w0.3: v1(-6.25,-2.75) -5.65,-3.35 -5.359,-3.35 -2.3,-6.409 -2.3,-17.225 ; v1(-5.75,-7.3) -5.2,-7.85 -5.2,-17.225
GND_P: H2.1 P2.1 | length 42.8
  Mid-Layer 1 w3.4: -24.8,-2 P2.1
  Mid-Layer 2 w3.4: -24.8,-2 P2.1
  Mid-Layer 4 w3.4: -24.8,-2 P2.1
  Bottom Layer w3.4: -24.8,-2 P2.1
GPI1: P7.47 | length 15.2
  Top Layer w0.2: v1(-12.55,1.75) P7.47
  Mid-Layer 2 w0.2: -26.4,1.75 v1(-12.55,1.75)
GPI2: P7.49 | length 15.2
  Top Layer w0.2: v1(-13.05,2.25) P7.49
  Mid-Layer 2 w0.2: -26.4,2.25 v1(-13.05,2.25)
GPI3: P7.53 | length 15.2
  Top Layer w0.2: v1(-13.05,3.25) P7.53
  Mid-Layer 2 w0.2: -26.4,3.25 v1(-13.05,3.25)
GPI4: P7.58 | length 23.1
  Top Layer w0.2: P7.58 v1(-5.75,4.25)
  Mid-Layer 2 w0.2: -26.4,5.6 -12.198,5.6 -10.848,4.25 v1(-5.75,4.25)
GPO1: P7.55 | length 15.2
  Top Layer w0.2: v1(-12.55,3.75) P7.55
  Mid-Layer 2 w0.2: -26.4,3.75 v1(-12.55,3.75)
GPO2: P7.56 | length 22.1
  Top Layer w0.2: P7.56 v1(-6.25,3.75)
  Mid-Layer 2 w0.2: -26.4,5.25 -12.343,5.25 -10.843,3.75 v1(-6.25,3.75)
GPO3: P7.57 | length 15.2
  Top Layer w0.2: v1(-13.05,4.25) P7.57
  Mid-Layer 2 w0.2: -26.4,4.25 v1(-13.05,4.25)
GPO4: P7.43 | length 15.2
  Top Layer w0.2: v1(-12.55,0.75) P7.43
  Mid-Layer 2 w0.2: -26.4,0.75 v1(-12.55,0.75)
HALL_1: P6.17 | length 15.3
  Top Layer w0.2: v1(-5.025,8.5) -4.975,8.55 -1.34,8.55 -0.25,9.64 P6.17
  Mid-Layer 2 w0.2: v1(-5.025,8.5) -4.813,8.5 -3.85,9.463 -3.85,17.225
HALL_2: P6.19 | length 20.3
  Top Layer w0.2: v1(-5.5,6.25) -5.5,6.257 -5,6.757 -5,7.805 -4.605,8.2 -1.19,8.2 0.25,9.64 P6.19
  Mid-Layer 2 w0.2: v1(-5.5,6.25) -5.5,7.318 -3.5,9.318 -3.5,17.225
HALL_3: P6.21 | length 20.1
  Top Layer w0.2: v1(-4.8,6.25) -4.65,6.4 -4.65,7.66 -4.46,7.85 -1.04,7.85 0.75,9.64 P6.21
  Mid-Layer 2 w0.2: v1(-4.8,6.25) -4.747,6.303 -4.747,7.576 -3.15,9.173 -3.15,17.225
MCB_IRQ: P7.26 | length 16.7
  Top Layer w0.2: P7.26 v1(-6.25,-3.75)
  Mid-Layer 2 w0.2: v1(-6.25,-3.75) -5.525,-3.75 -2.7,-6.575 -2.7,-17.225
MCB_SPI_CLK: P7.20 | length 14.8
  Top Layer w0.2: P7.20 v1(-5.75,-5.25)
  Mid-Layer 2 w0.2: v1(-5.75,-5.25) -5.548,-5.25 -3.75,-7.048 -3.75,-17.225
MCB_SPI_MISO: P7.14 | length 12.8
  Top Layer w0.2: P7.14 v1(-6.25,-6.75)
  Mid-Layer 2 w0.2: v1(-6.25,-6.75) -6.2,-6.8 -5.543,-6.8 -4.8,-7.543 -4.8,-17.225
MCB_SPI_MOSI: P7.16 | length 13.5
  Top Layer w0.2: P7.16 v1(-5.75,-6.25)
  Mid-Layer 2 w0.2: v1(-5.75,-6.25) -5.598,-6.25 -4.45,-7.398 -4.45,-17.225
MCB_SYNC0: P7.22 | length 15.4
  Top Layer w0.2: P7.22 v1(-6.25,-4.75)
  Mid-Layer 2 w0.2: v1(-6.25,-4.75) -5.543,-4.75 -3.4,-6.893 -3.4,-17.225
MCB_SYNC1: P7.24 | length 16.1
  Top Layer w0.2: P7.24 v1(-5.75,-4.25)
  Mid-Layer 2 w0.2: v1(-5.75,-4.25) -5.525,-4.25 -3.05,-6.725 -3.05,-17.225
MOTOR_TEMP: P6.13 | length 12.6
  Top Layer w0.2: v1(-5.5,10.95) -5.233,10.95 -4.65,10.367 -4.65,9.54 -4.46,9.35 -1.54,9.35 -1.25,9.64 P6.13
  Mid-Layer 2 w0.2: v1(-5.5,10.95) -5.5,17.225
PE1: H6.1
PE2: H7.1
PE3: H8.1
PE4: H9.1
PH_A: H5.1 P5.1 | length 53.5
  Mid-Layer 1 w3.4: P5.1 24.8,6
  Mid-Layer 2 w3.4: P5.1 24.8,6
  Mid-Layer 3 w3.4: P5.1 24.8,6
  Mid-Layer 4 w3.4: P5.1 24.8,6
  Bottom Layer w3.4: P5.1 24.8,6
PH_B: H4.1 P4.1 | length 53.5
  Mid-Layer 1 w3.4: P4.1 24.8,2
  Mid-Layer 2 w3.4: P4.1 24.8,2
  Mid-Layer 3 w3.4: P4.1 24.8,2
  Mid-Layer 4 w3.4: P4.1 24.8,2
  Bottom Layer w3.4: P4.1 24.8,2
PH_C: H3.1 P3.1 | length 53.5
  Mid-Layer 1 w3.4: P3.1 24.8,-2
  Mid-Layer 2 w3.4: P3.1 24.8,-2
  Mid-Layer 3 w3.4: P3.1 24.8,-2
  Mid-Layer 4 w3.4: P3.1 24.8,-2
  Bottom Layer w3.4: P3.1 24.8,-2
POW_SUP: H1.1 P1.1 | length 21.4
  Mid-Layer 3 w3.4: -24.8,-6 P1.1
  Bottom Layer w3.4: -24.8,-6 P1.1
PWM_BRAKE: P7.42 | length 30.9
  Top Layer w0.2: P7.42 v1(-6.25,0.25)
  Mid-Layer 2 w0.2: v1(-6.25,0.25) 4.7,0.25 8.525,4.075 8.525,17.225
pads on no net: B1.0 B1.1 B1.2 B1.3 B1.4 B1.5 B1.6 B1.7 B1.8 B1.9 B1.10 B1.11 B1.12 B1.13 B1.14 B1.15 B1.16 B1.17 B1.18 B1.19 B1.20 B1.21 B1.22 B1.23 B1.24 B1.25 B1.26 B1.27 B1.28 B1.29 B1.30 B1.31 B1.32 B1.33 B1.34 B1.35 B1.36 B1.37 B1.38 B1.39 B1.40 B1.41 B1.42 B1.43 B1.44 B1.45 B1.46 B1.47 B1.48 B1.49 B1.50 B1.51 B1.52 B1.53 B1.54 B1.55 B1.56 B1.57 B1.58 B1.59 B1.60 B1.61 B1.62 B1.63 B1.64 B1.65 B1.66 B1.67 B1.68 B1.69 B1.70 B1.71 B1.72 B1.73 B1.74 B1.75 B1.76 B1.77 B1.78 B1.79 B1.80 ORIGIN1.1 P6.3 P6.5 P6.7 P6.8 P6.9 P6.10 P6.11 P6.12 P6.14 P6.16 P6.18 P6.31 P6.33 P6.35 P6.37 P6.39 P6.41 P6.42 P6.43 P6.45 P6.46 P6.47 P6.48 P6.49 P6.50 P6.51 P6.52 P6.53 P6.54 P6.55 P6.56 P6.57 P6.58 P6.H1 P6.H2 P6.S1 P6.S2 P7.28 P7.29 P7.31 P7.35 P7.36 P7.40 P7.44 P7.45 P7.46 P7.48 P7.52 P7.54 P7.61 P7.62 P7.63 P7.64 P7.65 P7.66 P7.69 P7.70 P7.71 P7.72 P7.73 P7.74 P7.76 P7.78 P7.H1 P7.H2 P7.S1 P7.S2

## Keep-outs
Top Layer:
  lines w0.2: -10.502,-11.798 -10.397,-11.903 -8.403,-11.903 -8.298,-11.798 -8.298,-11.002 -8.403,-10.897 -10.397,-10.897 -10.502,-11.002 -10.502,-11.798 ; -10.502,11.002 -10.502,11.798 -10.397,11.903 -8.403,11.903 -8.298,11.798 -8.298,11.002 -8.403,10.897 -10.397,10.897 -10.502,11.002

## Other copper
Top Layer:
  pour cut-out: -17.75,-11.5 ccw(c-15.75,-11.5) -15.75,-13.5 1.075,-13.5 1.075,-11.5 -10.863,-11.5 cw(c-10.863,-10) -12.325,-10.337 ccw(c-15.25,-11) -14.669,-8.057 cw(c-14.4,-6.581) -15.9,-6.582 -15.9,6.582 cw(c-14.4,6.582) -14.669,8.058 ccw(c-15.249,11.001) -12.324,10.337 cw(c-10.863,10) -10.863,11.5 10.863,11.5 cw(c10.863,10) 12.325,10.337 ccw(c15.25,11) 14.669,8.057 cw(c14.4,6.581) 15.9,6.582 15.9,-6.582 cw(c14.4,-6.582) 14.669,-8.058 ccw(c15.249,-11.001) 12.324,-10.337 cw(c10.863,-10) 10.863,-11.5 1.075,-11.5 1.075,-13.5 15.75,-13.5 ccw(c15.75,-11.5) 17.75,-11.5 17.75,11.5 ccw(c15.75,11.5) 15.75,13.5 -15.75,13.5 ccw(c-15.75,11.5) -17.75,11.5

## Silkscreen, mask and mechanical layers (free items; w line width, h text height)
Drill Drawing:
  circle w0.254: c-42.968,29.662 r0.462
  lines w0.2: -44.296,26.496 44.528,26.496 ; -44.296,36.896 44.528,36.896 ; -38.951,24.416 -38.951,38.976 ; -34.553,24.416 -34.553,38.976 ; -24.865,24.416 -24.865,38.976 ; -20.721,24.416 -20.721,38.976 ; -14.689,24.416 -14.689,38.976 ; -3.252,24.416 -3.252,38.976 ; 1.692,24.416 1.692,38.976 ; 8.149,24.416 8.149,38.976 ; 17.519,24.416 17.519,38.976 ; 24.005,24.416 24.005,38.976 ; 34.09,24.416 34.09,38.976 ; -44.296,24.416 44.528,24.416 44.528,38.976 -44.296,38.976 -44.296,24.416
  lines w0.254: -43.43,27.12 -42.968,27.351 -42.506,27.12 -42.737,27.582 -42.506,28.044 -42.968,27.813 -43.43,28.044 -43.199,27.582 -43.43,27.12 ; -43.43,31.511 -43.199,31.511 -42.968,31.28 -42.737,31.511 -42.506,31.511 -42.737,31.742 -42.506,31.973 -42.737,31.973 -42.968,32.205 -43.199,31.973 -43.43,31.973 -43.199,31.742 -43.43,31.511 ; -43.43,34.285 -42.506,34.285 -42.968,33.36 -43.43,34.285 ; -43.43,35.44 -42.506,35.44 -42.506,36.365 -43.43,36.365 -43.43,35.44
  text "Symbol" at -43.048,37.52 h1.21
  text "Count" at -38.327,37.52 h1.21
  text "Hole Size" at -33.929,37.52 h1.21
  text "Plated" at -24.241,37.52 h1.21
  text "Hole Type" at -20.097,37.52 h1.21
  text "Drill Layer Pair" at -14.065,37.52 h1.21
  text "Via/Pad" at -2.628,37.52 h1.21
  text "Pad Shape" at 2.316,37.52 h1.21
  text "Template" at 8.773,37.52 h1.21
  text "Description" at 18.143,37.52 h1.21
  text "Hole Tolerance (+)" at 24.629,37.52 h1.21
  text "Hole Tolerance (-)" at 34.714,37.52 h1.21
  text "4" at -38.327,35.44 h1
  text "0,600mm (23,62mil)" at -33.929,35.44 h1
  text "NPTH" at -24.241,35.44 h1
  text "Round" at -20.097,35.44 h1
  text "Top Layer - Bottom Layer" at -14.065,35.44 h1
  text "Pad" at -2.628,35.44 h1
  text "Rounded" at 2.316,35.44 h1
  text "c0hn60" at 8.773,35.44 h1
  text "4" at -38.327,33.36 h1
  text "2,700mm (106,30mil)" at -33.929,33.36 h1
  text "PTH" at -24.241,33.36 h1
  text "Round" at -20.097,33.36 h1
  text "Top Layer - Bottom Layer" at -14.065,33.36 h1
  text "Pad" at -2.628,33.36 h1
  text "Rounded" at 2.316,33.36 h1
  text "c500h270" at 8.773,33.36 h1
  text "5" at -38.327,31.28 h1
  text "1,700mm (66,93mil)" at -33.929,31.28 h1
  text "PTH" at -24.241,31.28 h1
  text "Round" at -20.097,31.28 h1
  text "Top Layer - Bottom Layer" at -14.065,31.28 h1
  text "Pad" at -2.628,31.28 h1
  text "Rounded" at 2.316,31.28 h1
  text "c270h170m275p270" at 8.773,31.28 h1
  text "5" at -38.327,29.2 h1
  text "2,600mm (102,36mil)" at -33.929,29.2 h1
  text "PTH" at -24.241,29.2 h1
  text "Round" at -20.097,29.2 h1
  text "Top Layer - Bottom Layer" at -14.065,29.2 h1
  text "Pad" at -2.628,29.2 h1
  text "Rounded" at 2.316,29.2 h1
  text "c320h260" at 8.773,29.2 h1
  text "67" at -38.327,27.12 h1
  text "0,200mm (7,87mil)" at -33.929,27.12 h1
  text "PTH" at -24.241,27.12 h1
  text "Round" at -20.097,27.12 h1
  text "Top Layer - Bottom Layer" at -14.065,27.12 h1
  text "Via" at -2.628,27.12 h1
  text "Rounded" at 2.316,27.12 h1
  text "v50h20m40" at 8.773,27.12 h1
  text "85 Total" at -38.327,25.04 h1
